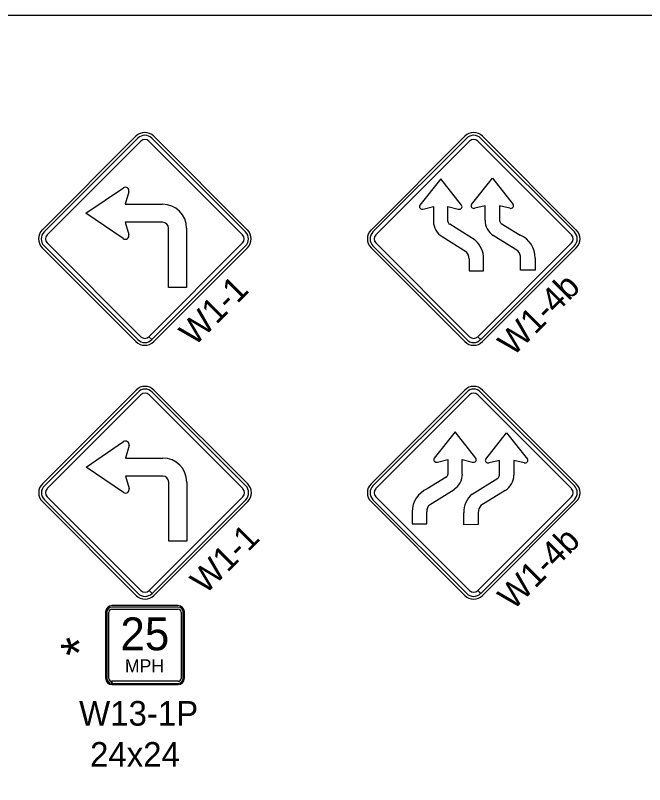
# Model space of a CAD drawing. Extents: x 1458 to 4498, y 17709 to 24109.
# Drawn here: x 2099.9 to 2482.6, y 23641.3 to 24109.1 of the extents above; entities that cross this region are included whole.
import ezdxf

# ---------------------------------------------------------------- set-up
doc = ezdxf.new("R2010")
doc.units = 0
doc.layers.add('P_TRAF_TCP_General', color=7, linetype='Continuous')

msp = doc.modelspace()

# ---------------------------------------------------------------- linework, layer by layer
at = {"layer": 'P_TRAF_TCP_General'}
for p, q in [((2173.24, 24035.63), (2116.24, 23978.62)), ((2241.1, 23978.62), (2184.09, 24035.63)), ((2373.24, 24035.63), (2316.24, 23978.62)), ((2441.1, 23978.62), (2384.09, 24035.63)), ((2174.43, 24034.44), (2117.42, 23977.44)), ((2174.43, 24034.44), (2117.42, 23977.44)), ((2119.19, 23975.67), (2176.19, 24032.68)), ((2119.19, 23975.67), (2176.19, 24032.68)), ((2181.14, 24032.68), (2238.15, 23975.67)), ((2181.14, 24032.68), (2238.15, 23975.67)), ((2239.91, 23977.44), (2182.91, 24034.44)), ((2239.91, 23977.44), (2182.91, 24034.44)), ((2374.43, 24034.44), (2317.42, 23977.44)), ((2374.43, 24034.44), (2317.42, 23977.44)), ((2319.19, 23975.67), (2376.19, 24032.68)), ((2319.19, 23975.67), (2376.19, 24032.68)), ((2381.14, 24032.68), (2438.15, 23975.67)), ((2381.14, 24032.68), (2438.15, 23975.67)), ((2439.91, 23977.44), (2382.91, 24034.44)), ((2439.91, 23977.44), (2382.91, 24034.44)), ((2358.65, 24009.66), (2346.01, 23993.67)), ((2371.28, 23993.67), (2358.65, 24009.66)), ((2377.39, 23994.18), (2390.02, 24010.17)), ((2390.02, 24010.17), (2402.63, 23994.21)), ((2142.78, 23988.82), (2165.58, 24004.26)), ((2168.95, 24001.88), (2166.75, 23994.31)), ((2166.75, 23994.31), (2189.42, 23994.31)), ((2377.39, 23994.18), (2377.39, 23994.18)), ((2385.57, 23993.37), (2379.38, 23991.83)), ((2385.57, 23984.52), (2385.57, 23993.37)), ((2400.66, 23991.83), (2394.4, 23993.39)), ((2394.4, 23993.39), (2394.4, 23984.36)), ((2165.54, 23973.4), (2142.78, 23988.82)), ((2348.01, 23991.32), (2354.2, 23992.86)), ((2354.2, 23992.86), (2354.2, 23983.81)), ((2363.02, 23983.85), (2363.02, 23992.88)), ((2363.02, 23992.88), (2369.28, 23991.32)), ((2189.42, 23983.33), (2166.75, 23983.33)), ((2166.75, 23983.33), (2168.92, 23975.86)), ((2193.1, 23943.71), (2193.1, 23979.65)), ((2204.08, 23979.65), (2204.08, 23943.71)), ((2379.66, 23972.37), (2364.07, 23982.12)), ((2395.44, 23982.63), (2406.91, 23975.46)), ((2359.45, 23974.6), (2374.23, 23965.36)), ((2405.6, 23965.87), (2390.59, 23975.25)), ((2176.19, 23913.72), (2119.19, 23970.72)), ((2238.15, 23970.72), (2181.16, 23913.74)), ((2238.15, 23970.72), (2181.16, 23913.74)), ((2376.19, 23913.72), (2319.19, 23970.72)), ((2438.15, 23970.72), (2381.16, 23913.74)), ((2438.15, 23970.72), (2381.16, 23913.74)), ((2116.24, 23967.77), (2173.24, 23910.77)), ((2117.42, 23968.96), (2174.43, 23911.95)), ((2117.42, 23968.96), (2174.43, 23911.95)), ((2182.93, 23911.97), (2239.91, 23968.96)), ((2182.93, 23911.97), (2239.91, 23968.96)), ((2184.09, 23910.77), (2241.1, 23967.77)), ((2316.24, 23967.77), (2373.24, 23910.77)), ((2317.42, 23968.96), (2374.43, 23911.95)), ((2317.42, 23968.96), (2374.43, 23911.95)), ((2382.93, 23911.97), (2439.91, 23968.96)), ((2382.93, 23911.97), (2439.91, 23968.96)), ((2384.09, 23910.77), (2441.1, 23967.77)), ((2375.86, 23961.11), (2375.85, 23953.77)), ((2384.67, 23953.76), (2384.68, 23961.05)), ((2407.22, 23954.28), (2407.23, 23961.63)), ((2416.06, 23961.59), (2416.05, 23954.27)), ((2375.85, 23953.77), (2384.67, 23953.76)), ((2416.05, 23954.27), (2407.22, 23954.28)), ((2204.08, 23943.71), (2193.1, 23943.71)), ((2182.91, 23911.95), (2181.14, 23913.72)), ((2182.91, 23911.95), (2181.14, 23913.72)), ((2181.16, 23913.74), (2182.93, 23911.97)), ((2181.16, 23913.74), (2182.93, 23911.97)), ((2382.91, 23911.95), (2381.14, 23913.72)), ((2382.91, 23911.95), (2381.14, 23913.72)), ((2381.16, 23913.74), (2382.93, 23911.97)), ((2381.16, 23913.74), (2382.93, 23911.97)), ((2173.36, 23881.27), (2116.35, 23824.27)), ((2241.21, 23824.27), (2184.21, 23881.27)), ((2373.24, 23881.27), (2316.24, 23824.27)), ((2441.1, 23824.27), (2384.09, 23881.27)), ((2174.54, 23880.09), (2117.54, 23823.08)), ((2119.3, 23821.32), (2176.31, 23878.32)), ((2181.26, 23878.32), (2238.26, 23821.32)), ((2240.03, 23823.08), (2183.02, 23880.09)), ((2374.43, 23880.09), (2317.42, 23823.08)), ((2374.43, 23880.09), (2317.42, 23823.08)), ((2319.19, 23821.32), (2376.19, 23878.32)), ((2319.19, 23821.32), (2376.19, 23878.32)), ((2381.14, 23878.32), (2438.15, 23821.32)), ((2381.14, 23878.32), (2438.15, 23821.32)), ((2439.91, 23823.08), (2382.91, 23880.09)), ((2439.91, 23823.08), (2382.91, 23880.09)), ((2367.31, 23855.83), (2354.71, 23839.87)), ((2379.95, 23839.84), (2367.31, 23855.83)), ((2386.05, 23839.33), (2398.69, 23855.32)), ((2398.69, 23855.32), (2411.32, 23839.33)), ((2142.89, 23834.46), (2165.69, 23849.91)), ((2169.06, 23847.52), (2166.87, 23839.95)), ((2166.87, 23839.95), (2189.54, 23839.95)), ((2356.68, 23837.49), (2362.94, 23839.05)), ((2362.94, 23839.05), (2362.94, 23830.02)), ((2371.76, 23830.18), (2371.76, 23839.03)), ((2371.76, 23839.03), (2377.95, 23837.49)), ((2379.95, 23839.84), (2379.95, 23839.84)), ((2165.66, 23819.04), (2142.89, 23834.46)), ((2394.31, 23838.54), (2388.05, 23836.98)), ((2394.31, 23829.51), (2394.31, 23838.54)), ((2409.33, 23836.98), (2403.14, 23838.52)), ((2403.14, 23838.52), (2403.14, 23829.47)), ((2189.54, 23828.97), (2166.87, 23828.97)), ((2166.87, 23828.97), (2169.03, 23821.5)), ((2193.21, 23789.36), (2193.21, 23825.3)), ((2204.19, 23825.3), (2204.19, 23789.36)), ((2361.89, 23828.29), (2350.42, 23821.12)), ((2377.67, 23818.03), (2393.27, 23827.78)), ((2351.73, 23811.53), (2366.74, 23820.91)), ((2397.89, 23820.26), (2383.11, 23811.02)), ((2176.31, 23759.36), (2119.3, 23816.37)), ((2238.26, 23816.37), (2181.27, 23759.38)), ((2376.19, 23759.36), (2319.19, 23816.37)), ((2438.15, 23816.37), (2381.16, 23759.38)), ((2438.15, 23816.37), (2381.16, 23759.38)), ((2116.35, 23813.42), (2173.36, 23756.41)), ((2117.54, 23814.6), (2174.54, 23757.6)), ((2183.04, 23757.62), (2240.03, 23814.6)), ((2184.21, 23756.41), (2241.21, 23813.42)), ((2316.24, 23813.42), (2373.24, 23756.41)), ((2317.42, 23814.6), (2374.43, 23757.6)), ((2317.42, 23814.6), (2374.43, 23757.6)), ((2382.93, 23757.62), (2439.91, 23814.6)), ((2382.93, 23757.62), (2439.91, 23814.6)), ((2384.09, 23756.41), (2441.1, 23813.42)), ((2341.28, 23807.25), (2341.29, 23799.93)), ((2350.11, 23799.94), (2350.1, 23807.29)), ((2372.66, 23799.42), (2372.65, 23806.71)), ((2381.48, 23806.77), (2381.49, 23799.43)), ((2341.29, 23799.93), (2350.11, 23799.94)), ((2381.49, 23799.43), (2372.66, 23799.42)), ((2204.19, 23789.36), (2193.21, 23789.36)), ((2183.02, 23757.6), (2181.26, 23759.36)), ((2183.02, 23757.6), (2181.26, 23759.36)), ((2181.27, 23759.38), (2183.04, 23757.62)), ((2181.27, 23759.38), (2183.04, 23757.62)), ((2382.91, 23757.6), (2381.14, 23759.36)), ((2382.91, 23757.6), (2381.14, 23759.36)), ((2381.16, 23759.38), (2382.93, 23757.62)), ((2381.16, 23759.38), (2382.93, 23757.62)), ((2198.97, 23750.17), (2158.59, 23750.17)), ((2154.79, 23746.37), (2154.79, 23705.99)), ((2155.59, 23746.31), (2155.59, 23705.93)), ((2155.59, 23746.31), (2155.59, 23705.93)), ((2156.84, 23705.93), (2156.84, 23746.31)), ((2198.97, 23749.31), (2158.59, 23749.31)), ((2198.97, 23749.31), (2158.59, 23749.31)), ((2158.59, 23748.06), (2198.97, 23748.06)), ((2200.72, 23746.31), (2200.72, 23705.93)), ((2201.97, 23705.93), (2201.97, 23746.31)), ((2201.97, 23705.93), (2201.97, 23746.31)), ((2202.77, 23705.99), (2202.77, 23746.37)), ((2158.59, 23702.93), (2158.59, 23704.18)), ((2198.97, 23704.18), (2158.6, 23704.18)), ((2158.6, 23704.18), (2158.6, 23702.93)), ((2158.59, 23702.93), (2198.97, 23702.93)), ((2158.59, 23702.19), (2198.97, 23702.19)), ((2158.6, 23702.93), (2198.97, 23702.93))]:
    msp.add_line(p, q, dxfattribs=at)
msp.add_lwpolyline([(4498.44, 24109.14), (1458.44, 24109.14), (1458.44, 22109.14), (4498.44, 22109.14)], close=True, dxfattribs=at)
for centre, radius, start, end in [((2178.67, 24030.2), 7.67, 45, 135), ((2178.67, 24030.2), 6, 45, 135), ((2178.67, 24030.2), 6, 45, 135), ((2378.67, 24030.2), 7.67, 45, 135), ((2378.67, 24030.2), 6, 45, 135), ((2378.67, 24030.2), 6, 45, 135), ((2178.67, 24030.2), 3.5, 45, 135), ((2178.67, 24030.2), 3.5, 45, 135), ((2378.67, 24030.2), 3.5, 45, 135), ((2378.67, 24030.2), 3.5, 45, 135), ((2166.81, 24002.44), 2.2, 345.3263, 124.1134), ((2189.42, 23979.65), 14.65, 0, 90), ((2365.12, 23983.94), 10.93, 180.6628, 238.6922), ((2365.12, 23983.94), 2.1, 182.2287, 239.8806), ((2396.5, 23984.45), 10.93, 179.6179, 237.2958), ((2396.5, 23984.45), 2.1, 182.4295, 239.8797), ((2189.42, 23979.65), 3.67, 0, 90), ((2121.66, 23973.2), 7.67, 135, 225), ((2121.66, 23973.2), 6, 135, 225), ((2121.66, 23973.2), 6, 135, 225), ((2121.66, 23973.2), 3.5, 135, 225), ((2121.66, 23973.2), 3.5, 135, 225), ((2166.81, 23975.2), 2.2, 234.773, 17.4627), ((2235.67, 23973.2), 3.5, 315, 45), ((2235.67, 23973.2), 3.5, 315, 45), ((2235.67, 23973.2), 6, 315, 45), ((2235.67, 23973.2), 6, 315, 45), ((2235.67, 23973.2), 7.67, 315, 45), ((2321.66, 23973.2), 7.67, 135, 225), ((2321.66, 23973.2), 6, 135, 225), ((2321.66, 23973.2), 6, 135, 225), ((2321.66, 23973.2), 3.5, 135, 225), ((2321.66, 23973.2), 3.5, 135, 225), ((2401.2, 23961.75), 14.85, 359.3947, 67.4081), ((2435.67, 23973.2), 3.5, 315, 45), ((2435.67, 23973.2), 3.5, 315, 45), ((2435.67, 23973.2), 6, 315, 45), ((2435.67, 23973.2), 6, 315, 45), ((2435.67, 23973.2), 7.67, 315, 45), ((2369.83, 23961.24), 14.85, 359.2809, 48.5613), ((2369.93, 23961.27), 5.93, 358.3973, 43.563), ((2401.3, 23961.78), 5.93, 358.5119, 43.5629), ((2178.67, 23916.19), 3.5, 225, 315), ((2178.67, 23916.19), 3.5, 225, 315), ((2378.67, 23916.19), 3.5, 225, 315), ((2378.67, 23916.19), 3.5, 225, 315), ((2178.67, 23916.19), 7.67, 225, 315), ((2178.67, 23916.19), 6, 225, 315), ((2178.67, 23916.19), 6, 225, 315), ((2378.67, 23916.19), 7.67, 225, 315), ((2378.67, 23916.19), 6, 225, 315), ((2378.67, 23916.19), 6, 225, 315), ((2178.78, 23875.85), 7.67, 45, 135), ((2178.78, 23875.85), 6, 45, 135), ((2378.67, 23875.85), 7.67, 45, 135), ((2378.67, 23875.85), 6, 45, 135), ((2378.67, 23875.85), 6, 45, 135), ((2178.78, 23875.85), 3.5, 45, 135), ((2378.67, 23875.85), 3.5, 45, 135), ((2378.67, 23875.85), 3.5, 45, 135), ((2166.93, 23848.08), 2.2, 345.3263, 124.1134), ((2189.54, 23825.3), 14.65, 0, 90), ((2360.84, 23830.11), 2.1, 300.1203, 357.5705), ((2360.84, 23830.11), 10.93, 302.7042, 0.3821), ((2392.21, 23829.6), 2.1, 300.1194, 357.7713), ((2392.21, 23829.6), 10.93, 301.3078, 359.3372), ((2189.54, 23825.3), 3.67, 0, 90), ((2121.78, 23818.84), 7.67, 135, 225), ((2121.78, 23818.84), 6, 135, 225), ((2121.78, 23818.84), 6, 135, 225), ((2121.78, 23818.84), 3.5, 135, 225), ((2121.78, 23818.84), 3.5, 135, 225), ((2166.93, 23820.84), 2.2, 234.773, 17.4627), ((2235.79, 23818.84), 3.5, 315, 45), ((2235.79, 23818.84), 3.5, 315, 45), ((2235.79, 23818.84), 6, 315, 45), ((2235.79, 23818.84), 6, 315, 45), ((2235.79, 23818.84), 7.67, 315, 45), ((2321.66, 23818.84), 7.67, 135, 225), ((2321.66, 23818.84), 6, 135, 225), ((2321.66, 23818.84), 6, 135, 225), ((2321.66, 23818.84), 3.5, 135, 225), ((2321.66, 23818.84), 3.5, 135, 225), ((2356.13, 23807.41), 14.85, 112.5919, 180.6053), ((2435.67, 23818.84), 3.5, 315, 45), ((2435.67, 23818.84), 3.5, 315, 45), ((2435.67, 23818.84), 6, 315, 45), ((2435.67, 23818.84), 6, 315, 45), ((2435.67, 23818.84), 7.67, 315, 45), ((2387.5, 23806.9), 14.85, 131.4387, 180.7191), ((2356.03, 23807.45), 5.93, 136.4371, 181.4881), ((2387.41, 23806.93), 5.93, 136.437, 181.6027), ((2178.78, 23761.84), 3.5, 225, 315), ((2378.67, 23761.84), 3.5, 225, 315), ((2378.67, 23761.84), 3.5, 225, 315), ((2178.78, 23761.84), 7.67, 225, 315), ((2178.78, 23761.84), 6, 225, 315), ((2378.67, 23761.84), 7.67, 225, 315), ((2378.67, 23761.84), 6, 225, 315), ((2378.67, 23761.84), 6, 225, 315), ((2158.59, 23746.37), 3.8, 90, 180), ((2198.97, 23746.37), 3.8, 0, 90), ((2158.59, 23746.31), 3, 90, 180), ((2158.59, 23746.31), 3, 90, 180), ((2158.59, 23746.31), 1.75, 90, 180), ((2198.97, 23746.31), 3, 0, 90), ((2198.97, 23746.31), 3, 0, 90), ((2198.97, 23746.31), 1.75, 0, 90), ((2158.59, 23705.99), 3.8, 180, 270), ((2158.59, 23705.93), 3, 180, 270), ((2158.59, 23705.93), 3, 180, 270), ((2158.59, 23705.93), 1.75, 180, 270), ((2198.97, 23705.99), 3.8, 270, 0), ((2198.97, 23705.93), 3, 270, 0), ((2198.97, 23705.93), 3, 270, 0), ((2198.97, 23705.93), 1.75, 270, 0)]:
    msp.add_arc(centre, radius, start, end, dxfattribs=at)
for centre, major_axis, start_param, end_param in [((2347.51, 23992.81), (1.8, 0), 2.546183, 4.994883), ((2369.79, 23992.81), (1.8, 0), 4.429945, 6.875191), ((2378.88, 23993.32), (1.8, 0), 2.546183, 4.994883), ((2401.16, 23993.32), (1.8, 0), 4.429945, 6.902987), ((2356.17, 23838.98), (-1.8, 0), 5.663384, 8.136425), ((2378.45, 23838.98), (-1.8, 0), 1.288302, 3.737003), ((2387.55, 23838.47), (-1.8, 0), 5.69118, 8.136425), ((2409.83, 23838.47), (-1.8, 0), 1.288302, 3.737003)]:
    msp.add_ellipse(centre, major_axis=major_axis, ratio=0.857143, start_param=start_param, end_param=end_param, dxfattribs=at)

# ---------------------------------------------------------------- texts
for s, height, rotation, p in [('W1-1', 14.994, 45, (2208.82, 23907.47)), ('W1-4b', 14.994, 45, (2402.58, 23901.24)), ('W1-1', 14.994, 45, (2215.52, 23756.53)), ('W1-4b', 14.994, 45, (2402.58, 23746.88)), ('*', 22.14, 90, (2149.88, 23719.64))]:
    msp.add_text(s, height=height, rotation=rotation, dxfattribs=at).set_placement(p)
for s, height, p in [('25', 19.992, (2163.79, 23723.02)), ('MPH', 7.997, (2166.56, 23709.53)), ('W13-1P', 14.994, (2138.67, 23677.2)), ('24x24', 14.994, (2145.34, 23652.21))]:
    msp.add_text(s, height=height, dxfattribs=at).set_placement(p)

doc.saveas('drawing.dxf')
